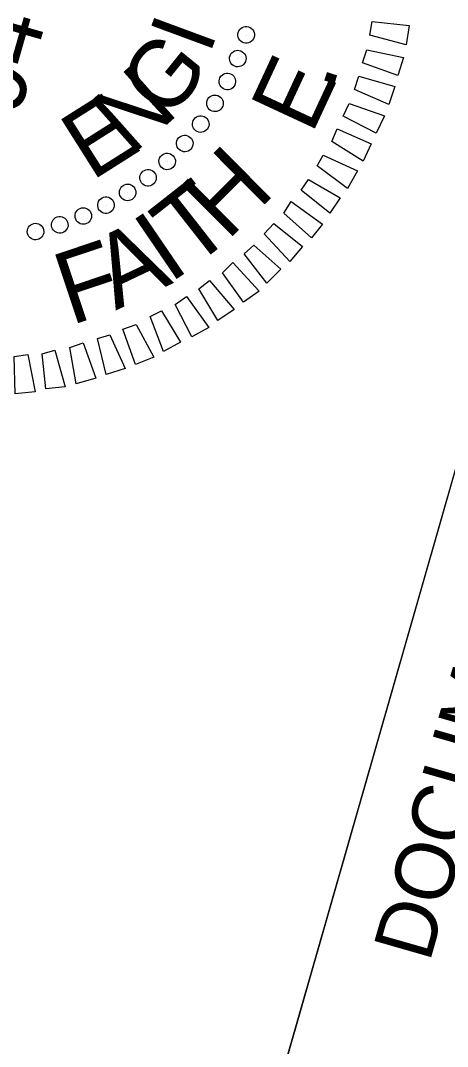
# Model space of a CAD drawing. Extents: x 2096093 to 2098911, y 683546 to 689764.
# Drawn here: x 2097575.6 to 2097612.7, y 689387.8 to 689477.1 of the extents above; entities that cross this region are included whole.
import ezdxf

# ---------------------------------------------------------------- set-up
doc = ezdxf.new("R2010")
doc.units = 0
for name, color, linetype in [('Old_Level_2', 7, 'Continuous'), ('Sheet PE Seal Cell', 7, 'Continuous'), ('Sheet Sticker Exception Certification CELL', 7, 'Continuous')]:
    doc.layers.add(name, color=color, linetype=linetype)

msp = doc.modelspace()

# ---------------------------------------------------------------- linework, layer by layer
at = {"layer": 'Old_Level_2'}
msp.add_lwpolyline([(2097489.395, 689409.442), (2097540.862, 689589.165), (2097647.935, 689558.502), (2097596.468, 689378.78)], close=True, dxfattribs=at)
msp.add_lwpolyline([(2097489.395, 689409.442), (2097540.862, 689589.165), (2097647.935, 689558.502), (2097596.468, 689378.78)], close=True, dxfattribs=at)
at = {"layer": 'Sheet PE Seal Cell'}
for p, q in [((2097595.232, 689475.798), (2097595.232, 689475.798)), ((2097594.482, 689473.724), (2097594.482, 689473.724)), ((2097593.554, 689471.754), (2097593.554, 689471.754)), ((2097592.544, 689469.859), (2097592.544, 689469.859)), ((2097591.293, 689468.032), (2097591.293, 689468.032)), ((2097589.877, 689466.357), (2097589.877, 689466.357)), ((2097588.379, 689464.758), (2097588.379, 689464.758)), ((2097586.682, 689463.371), (2097586.682, 689463.371)), ((2097584.902, 689462.06), (2097584.902, 689462.06)), ((2097583.034, 689460.983), (2097583.034, 689460.983)), ((2097581.035, 689459.995), (2097581.035, 689459.995)), ((2097579.008, 689459.275), (2097579.008, 689459.275)), ((2097576.865, 689458.692), (2097576.865, 689458.692))]:
    msp.add_line(p, q, dxfattribs=at)
for points in [[(2097606.18, 689476.981), (2097609.408, 689476.629), (2097609.132, 689474.939), (2097605.994, 689475.786)], [(2097605.733, 689474.508), (2097608.926, 689473.854), (2097608.424, 689472.282), (2097605.354, 689473.369)], [(2097605.024, 689472.215), (2097608.149, 689471.32), (2097607.646, 689469.748), (2097604.646, 689471.075)], [(2097604.192, 689469.853), (2097607.261, 689468.766), (2097606.519, 689467.262), (2097603.669, 689468.754)], [(2097603.147, 689467.655), (2097606.099, 689466.342), (2097605.405, 689464.825), (2097602.672, 689466.543)], [(2097601.916, 689465.355), (2097604.903, 689463.98), (2097604.051, 689462.456), (2097601.387, 689464.415)], [(2097600.631, 689463.227), (2097603.405, 689461.653), (2097602.498, 689460.3), (2097600.005, 689462.314)], [(2097599.146, 689461.311), (2097601.858, 689459.339), (2097600.896, 689458.158), (2097598.493, 689460.302)], [(2097597.614, 689459.41), (2097600.106, 689457.396), (2097599.006, 689456.099), (2097596.782, 689458.504)], [(2097595.875, 689457.515), (2097598.244, 689455.433), (2097597.014, 689454.225), (2097595.037, 689456.767)], [(2097594.041, 689456.012), (2097596.347, 689453.531), (2097594.98, 689452.57), (2097593.161, 689455.119)], [(2097592.035, 689454.454), (2097594.169, 689451.918), (2097592.754, 689450.971), (2097591.1, 689453.733)], [(2097590.022, 689453.054), (2097591.957, 689450.367), (2097590.473, 689449.544), (2097589.039, 689452.347)], [(2097587.844, 689451.805), (2097589.511, 689449.091), (2097588.027, 689448.268), (2097586.868, 689451.304)], [(2097585.632, 689450.618), (2097587.162, 689447.787), (2097585.575, 689447.149), (2097584.478, 689450.22)], [(2097583.344, 689449.712), (2097584.689, 689446.779), (2097583.033, 689446.265), (2097582.266, 689449.397)], [(2097578.543, 689448.382), (2097579.455, 689445.209), (2097577.786, 689445.011), (2097577.464, 689448.067)], [(2097581.016, 689449.027), (2097582.113, 689445.956), (2097580.409, 689445.456), (2097579.862, 689448.629)], [(2097576.201, 689448.013), (2097576.831, 689444.764), (2097575.114, 689444.579), (2097575.005, 689447.835)]]:
    msp.add_lwpolyline(points, close=True, dxfattribs=at)
for centre, major_axis in [((2097595.213, 689475.816), (0.689, -0.21)), ((2097594.483, 689473.754), (0.668, -0.269)), ((2097593.577, 689471.762), (0.642, -0.327)), ((2097592.5, 689469.857), (0.611, -0.381)), ((2097591.262, 689468.054), (0.575, -0.433)), ((2097589.871, 689466.365), (0.535, -0.482)), ((2097588.338, 689464.804), (0.491, -0.526)), ((2097586.675, 689463.382), (0.444, -0.567)), ((2097584.894, 689462.111), (0.392, -0.604)), ((2097583.009, 689460.999), (0.338, -0.636)), ((2097581.035, 689460.056), (0.282, -0.663)), ((2097578.986, 689459.289), (0.223, -0.685)), ((2097576.878, 689458.704), (0.162, -0.701))]:
    msp.add_ellipse(centre, major_axis=major_axis, ratio=0.999708, dxfattribs=at)
at = {"layer": 'Sheet Sticker Exception Certification CELL'}
msp.add_line((2097596.468, 689378.78), (2097647.885, 689558.326), dxfattribs=at)
msp.add_line((2097596.468, 689378.78), (2097647.885, 689558.326), dxfattribs=at)

# ---------------------------------------------------------------- texts
at = {"layer": 'Sheet PE Seal Cell'}
for s, height, rotation, p in [('046981', 5.9982, 74.02589, (2097575.354, 689468.464)), ('I', 5.648, 69.72709, (2097592.017, 689474.014)), ('G', 5.852, 51.01613, (2097588.388, 689468.24)), ('E', 6.044, 65.08358, (2097600.92, 689467.069)), ('N', 5.95, 41.65984, (2097585.179, 689465.206)), ('.', 6, 72.19292, (2097602.68, 689470.868)), ('E', 5.983, 32.30278, (2097581.757, 689463.065)), ('H', 6.3, 44.89924, (2097593.551, 689457.81)), ('T', 6.352, 38.099, (2097590.395, 689455.345)), ('I', 6.364, 34.29705, (2097588.51, 689454.135)), ('A', 6.345, 25.45674, (2097583.847, 689451.823)), ('F', 6.29, 18.44013, (2097579.927, 689450.515))]:
    msp.add_text(s, height=height, rotation=rotation, dxfattribs=at).set_placement(p)
at = {"layer": 'Sheet Sticker Exception Certification CELL'}
msp.add_text('DOCUMENT NOT CONSIDERED FINAL', height=5.13504, rotation=74.01987, dxfattribs=at).set_placement((2097611.17, 689395.033))
msp.add_text('DOCUMENT NOT CONSIDERED FINAL', height=5.13504, rotation=74.01987, dxfattribs=at).set_placement((2097611.17, 689395.033))

doc.saveas('drawing.dxf')
